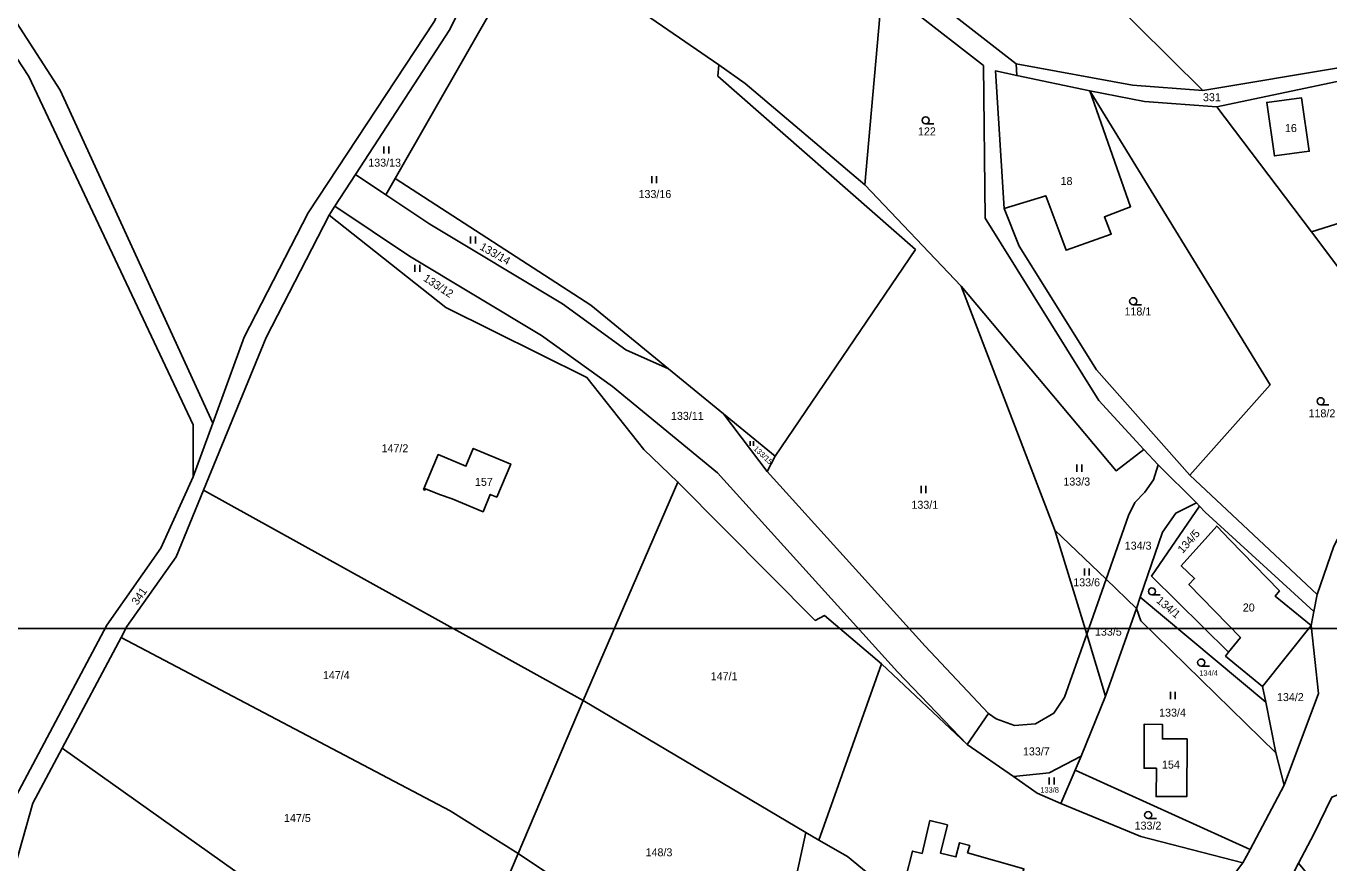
# Model space of a CAD drawing. Extents: x -590606 to -587796, y -1065936 to -1062515.
# Drawn here: x -589263.5 to -588986.8, y -1064054.7 to -1063876.9 of the extents above; entities that cross this region are included whole.
import ezdxf

# ---------------------------------------------------------------- set-up
doc = ezdxf.new("R2010")
doc.units = 0
for name, color, linetype in [('Default', 7, 'Continuous'), ('Parcela nároku', 7, 'Continuous'), ('Vrstva 30', 7, 'Continuous')]:
    doc.layers.add(name, color=color, linetype=linetype)

msp = doc.modelspace()

# ---------------------------------------------------------------- linework, layer by layer
at = {"layer": 'Default'}
msp.add_lwpolyline([(-590606.42, -1064004.87), (-587796.29, -1064004.87), (-587796.29, -1065935.82), (-590606.42, -1065935.82)], close=True, dxfattribs=at)
at = {"layer": 'Parcela nároku'}
for points in [[(-589307.9, -1063655.2), (-589326.33, -1063733.9), (-589327.09, -1063739.85), (-589328.28, -1063750.21), (-589327.35, -1063772.85), (-589317.19, -1063796.08), (-589256.24, -1063890.49), (-589223.79, -1063961.26), (-589228.02, -1063972.63), (-589228.02, -1063961.61), (-589262.9, -1063887.63), (-589320.58, -1063799.46), (-589331.2, -1063772.73), (-589332.78, -1063749.35), (-589331.14, -1063737.89), (-589330.1, -1063732.43), (-589312.33, -1063655.31)], [(-589415.32, -1064168.15), (-589348.65, -1064220.94), (-589342.52, -1064231.73), (-589341.32, -1064229.23), (-589330.47, -1064221.55), (-589321.03, -1064204.69), (-589297.69, -1064139.02), (-589287.98, -1064118.63), (-589265.69, -1064040.57), (-589246.35, -1064004.19), (-589234.85, -1063987.83), (-589228.02, -1063972.63), (-589228.02, -1063961.61), (-589262.9, -1063887.63), (-589320.58, -1063799.46), (-589331.2, -1063772.73), (-589332.78, -1063749.35), (-589331.14, -1063737.89), (-589383.17, -1063717.01), (-589403.24, -1063706.74), (-589431.69, -1063702.42)], [(-589161.69, -1063853.54), (-589173.52, -1063877.63), (-589193.54, -1063908.46), (-589197.9, -1063915.17), (-589199.13, -1063917.08), (-589212.47, -1063943.03), (-589225.79, -1063975.46), (-589231.61, -1063989.64), (-589242.07, -1064004.44), (-589243.31, -1064006.77), (-589255.83, -1064030.28), (-589262.05, -1064041.97), (-589268.61, -1064065.31), (-589280, -1064105.86), (-589283.23, -1064117.37), (-589294.51, -1064142.35), (-589296.1, -1064145.86), (-589313.27, -1064194.44), (-589318.75, -1064209.32), (-589328.06, -1064225.59), (-589336.07, -1064230.64), (-589340.72, -1064241.14), (-589343.02, -1064260.62), (-589338.01, -1064309.76)], [(-589075.07, -1063873.65), (-589060.17, -1063885.31), (-589059.79, -1063917.68), (-589035.68, -1063956.44), (-589026.08, -1063966.87), (-589023.08, -1063970.12), (-589014.92, -1063978.2), (-589014.3, -1063978.87), (-589013.08, -1063980.19), (-588989.98, -1064001.24), (-588989.28, -1063997.65), (-589016.29, -1063972.28), (-589036.13, -1063949.93), (-589052.55, -1063923.67), (-589055.75, -1063915.66), (-589057.63, -1063886.45), (-589053.07, -1063887.41), (-589053.21, -1063884.95), (-589069.14, -1063872.51)], [(-589341.19, -1064310.2), (-589345.86, -1064268.84), (-589346.68, -1064261.55), (-589345.6, -1064239.65), (-589342.52, -1064231.73), (-589341.32, -1064229.23), (-589330.47, -1064221.55), (-589321.03, -1064204.69), (-589297.69, -1064139.02), (-589287.98, -1064118.63), (-589265.69, -1064040.57), (-589246.35, -1064004.19), (-589234.85, -1063987.83), (-589228.02, -1063972.63), (-589223.79, -1063961.26), (-589217.17, -1063943.01), (-589203.59, -1063916.55), (-589176.77, -1063875.88)], [(-588985.76, -1063987.39), (-588989.28, -1063997.65), (-588989.98, -1064001.24), (-588990.57, -1064004.24), (-588988.98, -1064018.69), (-588996.29, -1064038.15), (-589003.54, -1064051.81), (-589005.05, -1064054.65), (-589016.73, -1064070.08)], [(-589016.73, -1064070.08), (-589005.05, -1064054.65), (-589026.71, -1064049.03), (-589043.73, -1064042.05), (-589048.77, -1064039.82), (-589053.78, -1064036.31), (-589063.6, -1064029.51), (-589081.82, -1064012.39), (-589095.15, -1064049.8), (-589089.04, -1064053.32), (-589074.28, -1064065.43)], [(-589082.83, -1064278.16), (-589065.83, -1064263.54), (-589057.56, -1064251.87), (-589052.83, -1064244.14), (-589044.53, -1064219.06), (-589031.52, -1064180.07), (-589020.7, -1064158.31), (-589014.12, -1064135.5), (-589010.47, -1064096.24), (-589004.27, -1064075.98), (-588993.27, -1064054.69), (-588989.95, -1064048.58), (-588986.17, -1064040.73)], [(-589076.74, -1064057.94), (-589075.19, -1064052.15), (-589073.19, -1064052.65), (-589071.51, -1064045.68), (-589067.81, -1064046.59), (-589069.28, -1064052.59), (-589066.01, -1064053.39), (-589065.25, -1064050.39), (-589063.07, -1064050.94), (-589063.51, -1064052.53), (-589051.55, -1064055.9)]]:
    msp.add_lwpolyline(points, dxfattribs=at)
for points in [[(-589327.09, -1063739.85), (-589157.4, -1063807.44), (-589159.46, -1063824.12), (-589167.48, -1063852.98), (-589176.77, -1063875.88), (-589203.59, -1063916.55), (-589217.17, -1063943.01), (-589223.79, -1063961.26), (-589256.24, -1063890.49), (-589317.19, -1063796.08), (-589327.35, -1063772.85), (-589328.28, -1063750.21)], [(-589128.36, -1063793.8), (-589145.4, -1063808.11), (-589134.69, -1063814.94), (-589108.21, -1063827.09), (-589102.02, -1063831.62), (-589090.13, -1063845.11), (-589069.14, -1063872.51), (-589053.21, -1063884.95), (-589028.49, -1063889.47), (-589013.53, -1063890.56), (-589041.47, -1063862.89), (-589082.22, -1063823.01), (-589103.91, -1063795.61)], [(-589111.09, -1063829.69), (-589104.16, -1063834.59), (-589081.3, -1063865.14), (-589085.38, -1063910.66), (-589110.75, -1063889.1), (-589116.38, -1063885.17), (-589130.81, -1063875.25), (-589121.59, -1063824.84)], [(-588969.91, -1063849.07), (-588968.27, -1063851.78), (-588958.1, -1063870.25), (-588952.08, -1063879.66), (-588956.54, -1063883.07), (-588968.03, -1063870.31), (-588977.4, -1063878.2), (-588978.32, -1063877.14), (-588983.46, -1063885.54), (-589013.53, -1063890.56), (-589041.47, -1063862.89), (-589017.13, -1063854.66), (-588978.91, -1063839.48), (-588976.89, -1063838.59), (-588971.47, -1063846.51)], [(-589161.69, -1063853.54), (-589173.52, -1063877.63), (-589193.54, -1063908.46), (-589187.09, -1063912.76), (-589185.12, -1063909.31), (-589155.67, -1063857.74)], [(-589185.12, -1063909.31), (-589155.67, -1063857.74), (-589130.81, -1063875.25), (-589116.38, -1063885.17), (-589116.56, -1063887.54), (-589074.59, -1063924.4), (-589104.36, -1063968.29), (-589115.33, -1063959.3), (-589127.03, -1063949.71), (-589143.54, -1063936.18)], [(-589081.3, -1063865.14), (-589085.38, -1063910.66), (-589064.92, -1063932.16), (-589031.97, -1063971.35), (-589026.08, -1063966.87), (-589035.68, -1063956.44), (-589059.79, -1063917.68), (-589060.17, -1063885.31), (-589075.07, -1063873.65)], [(-589028.49, -1063889.47), (-589013.53, -1063890.56), (-588983.46, -1063885.54), (-588978.32, -1063877.14), (-588977.4, -1063878.2), (-588976.4, -1063879.47), (-588977.05, -1063880.26), (-588981.38, -1063887.88), (-589010.57, -1063894.09), (-589025.93, -1063892.96), (-589037.53, -1063890.69), (-589053.07, -1063887.41), (-589053.21, -1063884.95)], [(-589010.57, -1063894.09), (-588981.38, -1063887.88), (-588977.05, -1063880.26), (-588973.04, -1063895.63), (-588966.91, -1063891.55), (-588956.54, -1063883.07), (-588952.08, -1063879.66), (-588939.65, -1063904.58), (-588990.51, -1063920.59)], [(-589104.36, -1063968.29), (-589106.09, -1063971.54), (-589072.55, -1064008.63), (-589059.05, -1064022.93), (-589057.44, -1064024.05), (-589053.53, -1064025.47), (-589049.12, -1064025.11), (-589045.24, -1064022.87), (-589042.92, -1064019.47), (-589038.21, -1064006.09), (-589044.98, -1063983.99), (-589064.92, -1063932.16), (-589085.38, -1063910.66), (-589110.75, -1063889.1), (-589116.38, -1063885.17), (-589116.56, -1063887.54), (-589074.59, -1063924.4)], [(-589034.45, -1063917.45), (-589033.02, -1063921.08), (-589042.59, -1063924.51), (-589043.93, -1063920.91), (-589046.93, -1063912.96), (-589055.75, -1063915.66), (-589057.63, -1063886.45), (-589053.07, -1063887.41), (-589037.53, -1063890.69), (-589028.89, -1063915.28)], [(-589043.93, -1063920.91), (-589046.93, -1063912.96), (-589055.75, -1063915.66), (-589052.55, -1063923.67), (-589036.13, -1063949.93), (-589016.29, -1063972.28), (-588999.26, -1063953.09), (-589037.53, -1063890.69), (-589028.89, -1063915.28), (-589034.45, -1063917.45), (-589033.02, -1063921.08), (-589042.59, -1063924.51)], [(-588999.26, -1063953.09), (-589016.29, -1063972.28), (-588989.28, -1063997.65), (-588985.76, -1063987.39), (-588983.36, -1063982.76), (-588973.8, -1063971.68), (-588960.88, -1063964.65), (-588983.18, -1063930.34), (-588990.51, -1063920.59), (-589010.57, -1063894.09), (-589025.93, -1063892.96), (-589037.53, -1063890.69)], [(-588999.98, -1063893.14), (-588992.6, -1063892.18), (-588990.94, -1063903.48), (-588998.37, -1063904.49)], [(-588998.37, -1063904.49), (-588999.98, -1063893.14), (-588992.6, -1063892.18), (-588990.94, -1063903.48)], [(-588959.37, -1063964.26), (-588960.88, -1063964.65), (-588983.18, -1063930.34), (-588990.51, -1063920.59), (-588939.65, -1063904.58), (-588933.62, -1063917.1), (-588931.41, -1063924.18), (-588928, -1063935.09), (-588924.53, -1063943.8), (-588923.06, -1063947.48), (-588943.02, -1063959.97)], [(-589136.1, -1063945.66), (-589149.58, -1063935.92), (-589177.76, -1063918.99), (-589187.09, -1063912.76), (-589193.54, -1063908.46), (-589197.9, -1063915.17), (-589182.04, -1063925.75), (-589153.99, -1063942.61), (-589138.96, -1063953.46), (-589116.61, -1063971.84), (-589078.41, -1064014.08), (-589063.6, -1064029.51), (-589059.05, -1064022.93), (-589072.55, -1064008.63), (-589106.09, -1063971.54), (-589115.33, -1063959.3), (-589127.03, -1063949.71)], [(-589187.09, -1063912.76), (-589185.12, -1063909.31), (-589143.54, -1063936.18), (-589127.03, -1063949.71), (-589136.1, -1063945.66), (-589149.58, -1063935.92), (-589177.76, -1063918.99)], [(-589138.96, -1063953.46), (-589116.61, -1063971.84), (-589078.41, -1064014.08), (-589063.6, -1064029.51), (-589081.82, -1064012.39), (-589093.93, -1064002.12), (-589095.88, -1064003.14), (-589125.06, -1063973.78), (-589132.28, -1063966.84), (-589144.39, -1063951.59), (-589174.35, -1063936.69), (-589199.13, -1063917.08), (-589197.9, -1063915.17), (-589182.04, -1063925.75), (-589153.99, -1063942.61)], [(-589144.39, -1063951.59), (-589132.28, -1063966.84), (-589125.06, -1063973.78), (-589145.14, -1064020.17), (-589225.79, -1063975.46), (-589212.47, -1063943.03), (-589199.13, -1063917.08), (-589174.35, -1063936.69)], [(-589026.08, -1063966.87), (-589023.08, -1063970.12), (-589024.01, -1063973.26), (-589025.91, -1063975.94), (-589027.99, -1063978.13), (-589029.32, -1063980.85), (-589034.1, -1063994.42), (-589044.98, -1063983.99), (-589064.92, -1063932.16), (-589031.97, -1063971.35)], [(-589115.33, -1063959.3), (-589104.36, -1063968.29), (-589106.09, -1063971.54)], [(-589178.67, -1063975.18), (-589175.67, -1063976.42), (-589172.99, -1063977.34), (-589166.44, -1063980.06), (-589164.89, -1063976.4), (-589163.52, -1063976.97), (-589160.56, -1063969.94), (-589168.51, -1063966.63), (-589170.08, -1063970.39), (-589175.97, -1063967.94), (-589179.06, -1063975.32), (-589178.79, -1063975.46)], [(-589175.97, -1063967.94), (-589179.06, -1063975.32), (-589178.79, -1063975.46), (-589178.67, -1063975.18), (-589175.67, -1063976.42), (-589172.99, -1063977.34), (-589166.44, -1063980.06), (-589164.89, -1063976.4), (-589163.52, -1063976.97), (-589160.56, -1063969.94), (-589168.51, -1063966.63), (-589170.08, -1063970.39)], [(-589027.99, -1063978.13), (-589025.91, -1063975.94), (-589024.01, -1063973.26), (-589023.08, -1063970.12), (-589014.92, -1063978.2), (-589019.31, -1063980.38), (-589022.14, -1063984.38), (-589026.87, -1063998.25), (-589027.68, -1064000.6), (-589034.1, -1063994.42), (-589029.32, -1063980.85)], [(-589231.61, -1063989.64), (-589225.79, -1063975.46), (-589145.14, -1064020.17), (-589158.97, -1064052.64), (-589173.42, -1064043.63), (-589243.31, -1064006.77), (-589242.07, -1064004.44)], [(-589095.88, -1064003.14), (-589093.93, -1064002.12), (-589081.82, -1064012.39), (-589095.15, -1064049.8), (-589097.91, -1064048.23), (-589145.14, -1064020.17), (-589125.06, -1063973.78)], [(-589024.45, -1063993.73), (-589008.08, -1064009.89), (-589008.74, -1064010.73), (-589000.88, -1064017.19), (-589000.19, -1064020.53), (-589026.87, -1063998.25), (-589022.14, -1063984.38), (-589019.31, -1063980.38), (-589014.92, -1063978.2), (-589014.3, -1063978.87)], [(-589014.3, -1063978.87), (-589024.45, -1063993.73), (-589008.08, -1064009.89), (-589005.59, -1064006.76), (-589016.5, -1063995.55), (-589015.32, -1063994.22), (-589018.13, -1063991.55), (-589010.6, -1063983.13), (-589007.81, -1063986.04), (-588997.31, -1063996.88), (-588998.21, -1063997.97), (-588990.57, -1064004.24), (-588989.98, -1064001.24), (-589013.08, -1063980.19)], [(-589044.98, -1063983.99), (-589034.1, -1063994.42), (-589038.21, -1064006.09)], [(-589008.08, -1064009.89), (-589005.59, -1064006.76), (-589016.5, -1063995.55), (-589015.32, -1063994.22), (-589018.13, -1063991.55), (-589010.6, -1063983.13), (-589007.81, -1063986.04), (-588997.31, -1063996.88), (-588998.21, -1063997.97), (-588990.57, -1064004.24), (-589000.88, -1064017.19), (-589008.74, -1064010.73)], [(-589034.1, -1063994.42), (-589027.68, -1064000.6), (-589034.2, -1064019.27), (-589038.21, -1064006.09)], [(-589026.87, -1063998.25), (-589027.68, -1064000.6), (-589026.73, -1064003.23), (-588998.06, -1064031.27), (-589000.19, -1064020.53)], [(-589027.68, -1064000.6), (-589026.73, -1064003.23), (-588998.06, -1064031.27), (-588996.29, -1064038.15), (-589003.54, -1064051.81), (-589040.66, -1064034.94), (-589039.4, -1064032.02), (-589034.2, -1064019.27)], [(-589255.83, -1064030.28), (-589243.31, -1064006.77), (-589173.42, -1064043.63), (-589158.97, -1064052.64), (-589172.94, -1064085.48), (-589216.44, -1064058.29)], [(-589034.2, -1064019.27), (-589038.21, -1064006.09), (-589042.92, -1064019.47), (-589045.24, -1064022.87), (-589049.12, -1064025.11), (-589053.53, -1064025.47), (-589057.44, -1064024.05), (-589059.05, -1064022.93), (-589063.6, -1064029.51), (-589053.78, -1064036.31), (-589046.19, -1064035.51), (-589039.4, -1064032.02)], [(-588990.57, -1064004.24), (-589000.88, -1064017.19), (-589000.19, -1064020.53), (-588998.06, -1064031.27), (-588996.29, -1064038.15), (-588988.98, -1064018.69)], [(-589097.91, -1064048.23), (-589145.14, -1064020.17), (-589158.97, -1064052.64), (-589117.94, -1064080.19), (-589106.41, -1064087.58)], [(-589016.89, -1064028.33), (-589016.98, -1064040.59), (-589023.48, -1064040.57), (-589023.43, -1064034.56), (-589026.04, -1064034.54), (-589026.01, -1064028.34), (-589026.05, -1064025.2), (-589022.1, -1064025.28), (-589022.13, -1064028.34)], [(-589022.13, -1064028.34), (-589016.89, -1064028.33), (-589016.98, -1064040.59), (-589023.48, -1064040.57), (-589023.43, -1064034.56), (-589026.04, -1064034.54), (-589026.01, -1064028.34), (-589026.05, -1064025.2), (-589022.1, -1064025.28)], [(-589268.61, -1064065.31), (-589262.05, -1064041.97), (-589255.83, -1064030.28), (-589216.44, -1064058.29), (-589172.94, -1064085.48), (-589184.92, -1064113.54), (-589213.99, -1064095.18)], [(-589053.78, -1064036.31), (-589046.19, -1064035.51), (-589039.4, -1064032.02), (-589040.66, -1064034.94), (-589043.73, -1064042.05), (-589048.77, -1064039.82)], [(-589040.66, -1064034.94), (-589003.54, -1064051.81), (-589005.05, -1064054.65), (-589026.71, -1064049.03), (-589043.73, -1064042.05)], [(-588989.95, -1064048.58), (-588993.27, -1064054.69), (-588988.57, -1064060.38), (-588977.56, -1064066.84), (-588967.16, -1064065.03), (-588961.8, -1064053.25), (-588966.81, -1064044.36), (-588980.54, -1064038.51), (-588986.17, -1064040.73)], [(-589095.15, -1064049.8), (-589097.91, -1064048.23), (-589106.41, -1064087.58), (-589090.2, -1064097.97), (-589074.28, -1064065.43), (-589089.04, -1064053.32)], [(-589065.25, -1064050.39), (-589066.01, -1064053.39), (-589069.28, -1064052.59), (-589067.81, -1064046.59), (-589071.51, -1064045.68), (-589073.19, -1064052.65), (-589075.19, -1064052.15), (-589076.74, -1064057.94), (-589070.1, -1064059.8), (-589073.23, -1064066.24), (-589054.03, -1064064.29), (-589051.55, -1064055.9), (-589063.51, -1064052.53), (-589063.07, -1064050.94)], [(-589106.41, -1064087.58), (-589117.94, -1064080.19), (-589158.97, -1064052.64), (-589172.94, -1064085.48), (-589116.44, -1064119.07), (-589103.47, -1064126.46), (-589090.2, -1064097.97)]]:
    msp.add_lwpolyline(points, close=True, dxfattribs=at)
at = {"layer": 'Vrstva 30'}
for p, q in [((-589070.67, -1063897.68), (-589072.42, -1063897.68)), ((-589187.49, -1063902.48), (-589187.49, -1063903.98)), ((-589186.46, -1063903.98), (-589186.46, -1063902.48)), ((-589130.58, -1063908.78), (-589130.58, -1063910.28)), ((-589129.56, -1063910.28), (-589129.56, -1063908.78)), ((-589169.09, -1063921.62), (-589169.09, -1063923.12)), ((-589168.07, -1063923.12), (-589168.07, -1063921.62)), ((-589180.9, -1063927.62), (-589180.9, -1063929.12)), ((-589179.88, -1063929.12), (-589179.88, -1063927.62)), ((-589026.6, -1063936.1), (-589028.35, -1063936.1)), ((-588986.79, -1063957.34), (-588988.54, -1063957.34)), ((-589109.7, -1063965.07), (-589109.7, -1063966.07)), ((-589109.01, -1063966.07), (-589109.01, -1063965.07)), ((-589040.29, -1063970.07), (-589040.29, -1063971.57)), ((-589039.27, -1063971.57), (-589039.27, -1063970.07)), ((-589073.41, -1063974.6), (-589073.41, -1063976.1)), ((-589072.39, -1063976.1), (-589072.39, -1063974.6)), ((-589038.72, -1063992.14), (-589038.72, -1063993.64)), ((-589037.7, -1063993.64), (-589037.7, -1063992.14)), ((-589022.62, -1063997.74), (-589024.37, -1063997.74)), ((-589012.16, -1064012.85), (-589013.91, -1064012.85)), ((-589020.42, -1064018.35), (-589020.42, -1064019.85)), ((-589019.4, -1064019.85), (-589019.4, -1064018.35)), ((-589046.18, -1064036.52), (-589046.18, -1064038.02)), ((-589045.16, -1064038.02), (-589045.16, -1064036.52)), ((-589023.42, -1064045.25), (-589025.17, -1064045.25))]:
    msp.add_line(p, q, dxfattribs=at)
for centre in [(-589072.42, -1063896.93), (-589028.35, -1063935.35), (-588988.54, -1063956.59), (-589024.37, -1063996.99), (-589013.91, -1064012.1), (-589025.17, -1064044.5)]:
    msp.add_circle(centre, 0.75, dxfattribs=at)

# ---------------------------------------------------------------- texts
at = {"layer": 'Parcela nároku'}
for s, height, p in [('331', 1.7, (-589013.53, -1063892.87)), ('122', 1.7, (-589074.06, -1063900.13)), ('16', 1.7, (-588996.12, -1063899.42)), ('133/13', 1.7, (-589190.81, -1063906.77)), ('18', 1.7, (-589043.77, -1063910.67)), ('133/16', 1.7, (-589133.41, -1063913.44)), ('118/1', 1.7, (-589030.2, -1063938.38)), ('133/11', 1.7, (-589126.52, -1063960.56)), ('118/2', 1.7, (-588991.11, -1063960.02)), ('147/2', 1.7, (-589187.99, -1063967.44)), ('157', 1.7, (-589168.15, -1063974.57)), ('133/3', 1.7, (-589043.18, -1063974.51)), ('133/1', 1.7, (-589075.45, -1063979.44)), ('134/3', 1.7, (-589030.15, -1063988.12)), ('133/6', 1.7, (-589041.08, -1063995.92)), ('20', 1.7, (-589005.07, -1064001.26)), ('133/5', 1.7, (-589036.47, -1064006.39)), ('147/4', 1.7, (-589200.44, -1064015.63)), ('147/1', 1.7, (-589118.08, -1064015.85)), ('134/4', 1.14, (-589014.31, -1064014.89)), ('134/2', 1.7, (-588997.81, -1064020.29)), ('133/4', 1.7, (-589022.84, -1064023.59)), ('133/7', 1.7, (-589051.77, -1064031.83)), ('154', 1.7, (-589022.23, -1064034.63)), ('133/8', 1.14, (-589048.07, -1064039.73)), ('147/5', 1.7, (-589208.71, -1064045.97)), ('133/2', 1.7, (-589028.05, -1064047.59)), ('148/3', 1.7, (-589131.91, -1064053.26))]:
    msp.add_text(s, height=height, dxfattribs=at).set_placement(p)
for s, height, rotation, p in [('133/14', 1.7, 330.3033, (-589167.29, -1063924.27)), ('133/12', 1.7, 326.6297, (-589179.28, -1063930.88)), ('133/15', 1.14, 316.9344, (-589109.09, -1063966.81)), ('134/5', 1.7, 48.2044, (-589017.83, -1063989.03)), ('341', 1.7, 55.4258, (-589239.84, -1064000.04)), ('134/1', 1.7, 320.1353, (-589023.58, -1063999.19))]:
    msp.add_text(s, height=height, rotation=rotation, dxfattribs=at).set_placement(p)

doc.saveas('drawing.dxf')
